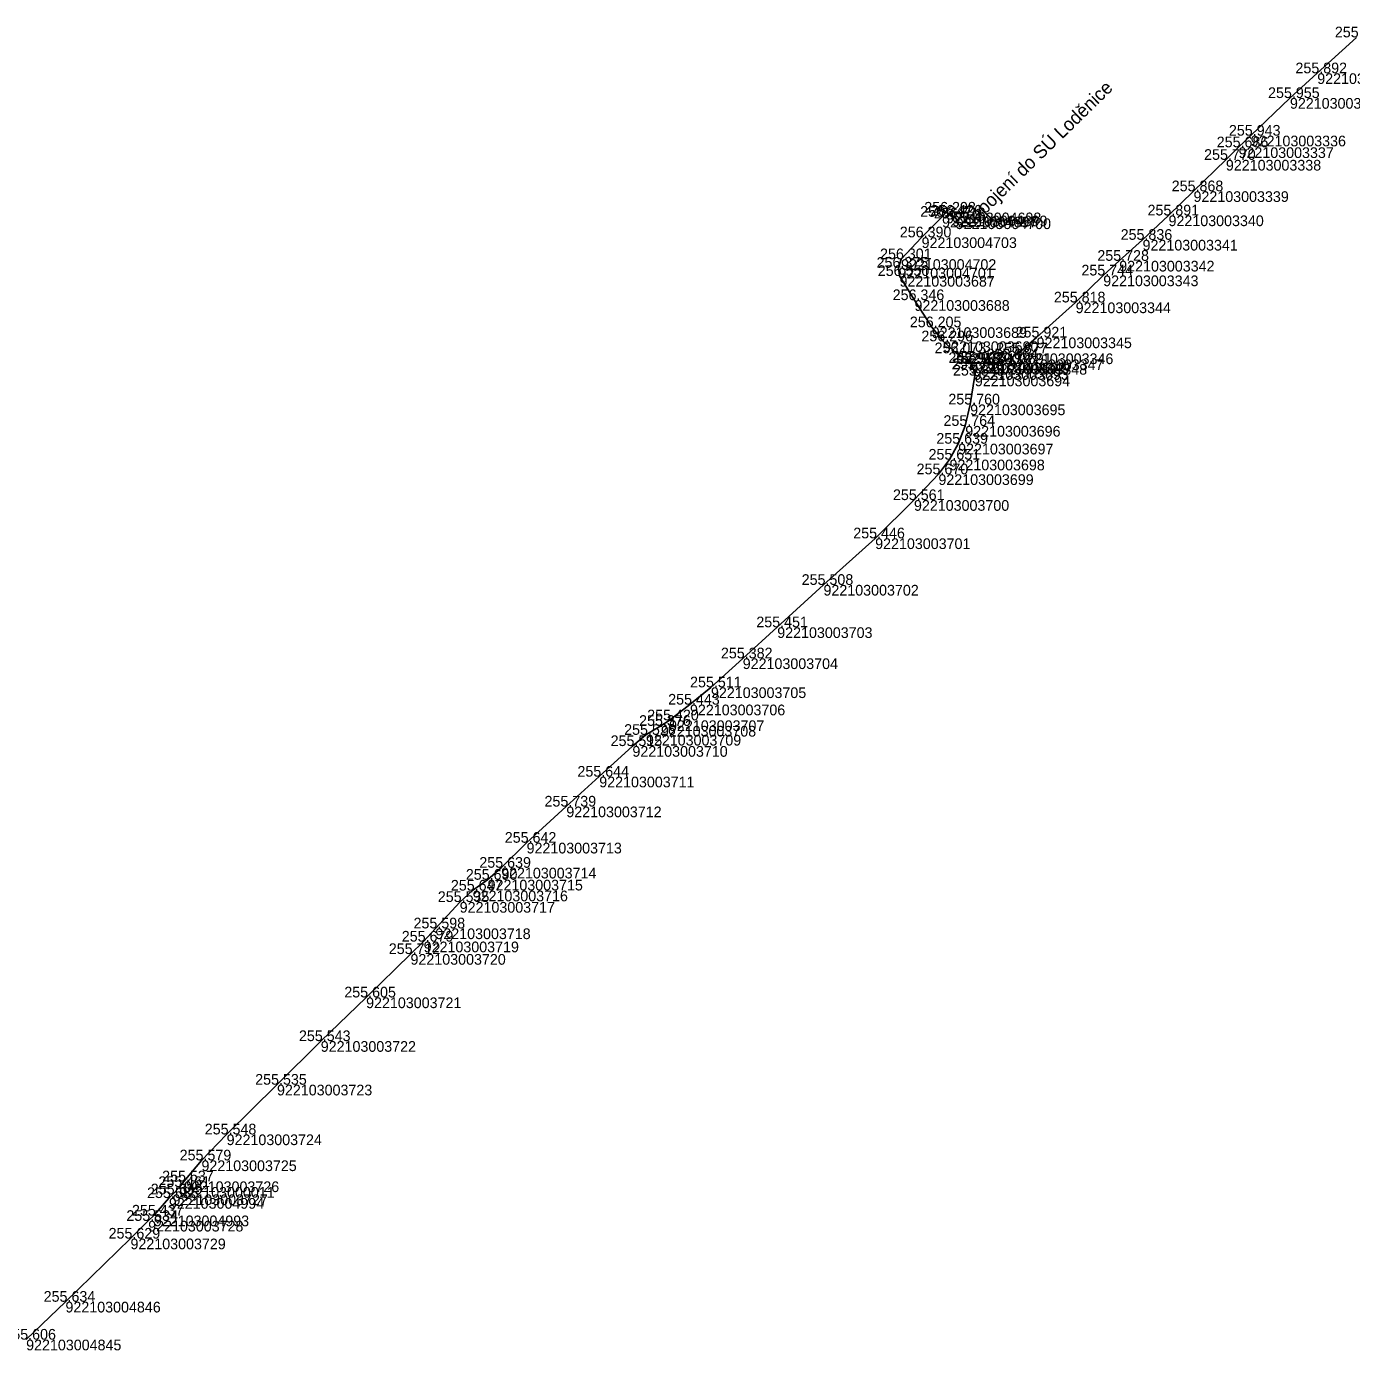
# Model space of a CAD drawing. Extents: x -771047 to -756200, y -1053876 to -1046520.
# Drawn here: x -762711.4 to -762562.5, y -1050999.9 to -1050851.1 of the extents above; entities that cross this region are included whole.
import ezdxf

# ---------------------------------------------------------------- set-up
doc = ezdxf.new("R2010")
doc.units = 0
for name, color, linetype in [('Vrstva 32', 7, 'Continuous'), ('Vrstva 60', 7, 'Continuous'), ('Vrstva 61', 7, 'Continuous'), ('Vrstva 63', 7, 'Continuous')]:
    doc.layers.add(name, color=color, linetype=linetype)

msp = doc.modelspace()

# ---------------------------------------------------------------- linework, layer by layer
at = {"layer": 'Vrstva 32'}
for points in [[(-762561.91, -1050852.33), (-762566.34, -1050856.37), (-762569.41, -1050859.15), (-762573.82, -1050863.38), (-762575.19, -1050864.69), (-762576.61, -1050866.1), (-762580.25, -1050869.63), (-762583.06, -1050872.35), (-762585.98, -1050875.09), (-762588.6, -1050877.45), (-762590.4, -1050879.1), (-762593.5, -1050882.13), (-762597.89, -1050886.07), (-762599.97, -1050887.86), (-762601.08, -1050888.54), (-762602.92, -1050889.05), (-762604.85, -1050888.89), (-762605.34, -1050888.93)], [(-762608.07, -1050872.03), (-762608.52, -1050872.5), (-762610.82, -1050874.81), (-762613.13, -1050877.27), (-762613.42, -1050878.23), (-762613.3, -1050879.15), (-762611.62, -1050881.87), (-762609.68, -1050884.92), (-762608.39, -1050886.5), (-762606.91, -1050887.84), (-762605.34, -1050888.93), (-762604.98, -1050889.63), (-762604.83, -1050890.35), (-762605.36, -1050893.6), (-762605.91, -1050896.01), (-762606.71, -1050898.01), (-762607.68, -1050899.8), (-762608.93, -1050901.45), (-762611.68, -1050904.35), (-762616.04, -1050908.65), (-762621.85, -1050913.88), (-762627.05, -1050918.65), (-762630.93, -1050922.14), (-762634.5, -1050925.4), (-762636.86, -1050927.34), (-762639.21, -1050929.11), (-762640.13, -1050929.73), (-762641.81, -1050930.74), (-762643.33, -1050932), (-762647.06, -1050935.44), (-762650.76, -1050938.8), (-762655.23, -1050942.87), (-762658.09, -1050945.68), (-762659.61, -1050947.03), (-762661.29, -1050948.25), (-762662.75, -1050949.53), (-762665.48, -1050952.5), (-762666.8, -1050953.98), (-762668.28, -1050955.38), (-762673.27, -1050960.26), (-762678.37, -1050965.17), (-762683.29, -1050970.07), (-762688.95, -1050975.66), (-762691.78, -1050978.58), (-762693.75, -1050980.94), (-762694.26, -1050981.57), (-762695.03, -1050982.4), (-762695.44, -1050982.81), (-762697.13, -1050984.78), (-762697.77, -1050985.38), (-762699.76, -1050987.37), (-762707.07, -1050994.47), (-762711.49, -1050998.73)], [(-762608.07, -1050872.03), (-762607.38, -1050872.37), (-762606.98, -1050872.68)]]:
    msp.add_lwpolyline(points, dxfattribs=at)
at = {"layer": 'Vrstva 60'}
for p, q in [((-762566.34, -1050856.37), (-762566.34, -1050856.37)), ((-762569.41, -1050859.15), (-762569.41, -1050859.15)), ((-762573.82, -1050863.38), (-762573.82, -1050863.38)), ((-762576.61, -1050866.1), (-762576.61, -1050866.1)), ((-762575.19, -1050864.69), (-762575.19, -1050864.69)), ((-762580.25, -1050869.63), (-762580.25, -1050869.63)), ((-762608.07, -1050872.03), (-762608.07, -1050872.03)), ((-762608.52, -1050872.5), (-762608.52, -1050872.5)), ((-762607.38, -1050872.37), (-762607.38, -1050872.37)), ((-762606.98, -1050872.68), (-762606.98, -1050872.68)), ((-762583.06, -1050872.35), (-762583.06, -1050872.35)), ((-762610.82, -1050874.81), (-762610.82, -1050874.81)), ((-762585.98, -1050875.09), (-762585.98, -1050875.09)), ((-762613.13, -1050877.27), (-762613.13, -1050877.27)), ((-762588.6, -1050877.45), (-762588.6, -1050877.45)), ((-762613.42, -1050878.23), (-762613.42, -1050878.23)), ((-762613.3, -1050879.15), (-762613.3, -1050879.15)), ((-762590.4, -1050879.1), (-762590.4, -1050879.1)), ((-762611.62, -1050881.87), (-762611.62, -1050881.87)), ((-762593.5, -1050882.13), (-762593.5, -1050882.13)), ((-762609.68, -1050884.92), (-762609.68, -1050884.92)), ((-762608.39, -1050886.5), (-762608.39, -1050886.5)), ((-762597.89, -1050886.07), (-762597.89, -1050886.07)), ((-762606.91, -1050887.84), (-762606.91, -1050887.84)), ((-762599.97, -1050887.86), (-762599.97, -1050887.86)), ((-762605.34, -1050888.93), (-762605.34, -1050888.93)), ((-762604.98, -1050889.63), (-762604.98, -1050889.63)), ((-762604.85, -1050888.89), (-762604.85, -1050888.89)), ((-762602.92, -1050889.05), (-762602.92, -1050889.05)), ((-762601.08, -1050888.54), (-762601.08, -1050888.54)), ((-762604.83, -1050890.35), (-762604.83, -1050890.35)), ((-762605.36, -1050893.6), (-762605.36, -1050893.6)), ((-762605.91, -1050896.01), (-762605.91, -1050896.01)), ((-762606.71, -1050898.01), (-762606.71, -1050898.01)), ((-762607.68, -1050899.8), (-762607.68, -1050899.8)), ((-762608.93, -1050901.45), (-762608.93, -1050901.45)), ((-762611.68, -1050904.35), (-762611.68, -1050904.35)), ((-762616.04, -1050908.65), (-762616.04, -1050908.65)), ((-762621.85, -1050913.88), (-762621.85, -1050913.88)), ((-762627.05, -1050918.65), (-762627.05, -1050918.65)), ((-762630.93, -1050922.14), (-762630.93, -1050922.14)), ((-762634.5, -1050925.4), (-762634.5, -1050925.4)), ((-762636.86, -1050927.34), (-762636.86, -1050927.34)), ((-762640.13, -1050929.73), (-762640.13, -1050929.73)), ((-762639.21, -1050929.11), (-762639.21, -1050929.11)), ((-762641.81, -1050930.74), (-762641.81, -1050930.74)), ((-762643.33, -1050932), (-762643.33, -1050932)), ((-762647.06, -1050935.44), (-762647.06, -1050935.44)), ((-762650.76, -1050938.8), (-762650.76, -1050938.8)), ((-762655.23, -1050942.87), (-762655.23, -1050942.87)), ((-762658.09, -1050945.68), (-762658.09, -1050945.68)), ((-762659.61, -1050947.03), (-762659.61, -1050947.03)), ((-762662.75, -1050949.53), (-762662.75, -1050949.53)), ((-762661.29, -1050948.25), (-762661.29, -1050948.25)), ((-762665.48, -1050952.5), (-762665.48, -1050952.5)), ((-762666.8, -1050953.98), (-762666.8, -1050953.98)), ((-762668.28, -1050955.38), (-762668.28, -1050955.38)), ((-762673.27, -1050960.26), (-762673.27, -1050960.26)), ((-762678.37, -1050965.17), (-762678.37, -1050965.17)), ((-762683.29, -1050970.07), (-762683.29, -1050970.07)), ((-762688.95, -1050975.66), (-762688.95, -1050975.66)), ((-762691.78, -1050978.58), (-762691.78, -1050978.58)), ((-762694.26, -1050981.57), (-762694.26, -1050981.57)), ((-762693.75, -1050980.94), (-762693.75, -1050980.94)), ((-762695.44, -1050982.81), (-762695.44, -1050982.81)), ((-762695.03, -1050982.4), (-762695.03, -1050982.4)), ((-762697.13, -1050984.78), (-762697.13, -1050984.78)), ((-762697.77, -1050985.38), (-762697.77, -1050985.38)), ((-762699.76, -1050987.37), (-762699.76, -1050987.37)), ((-762707.07, -1050994.47), (-762707.07, -1050994.47))]:
    msp.add_line(p, q, dxfattribs=at)

# ---------------------------------------------------------------- texts
for s, p in [('922103003334', (-762566.34, -1050857.57)), ('922103003335', (-762569.41, -1050860.35)), ('922103003336', (-762573.82, -1050864.58)), ('922103003338', (-762576.61, -1050867.3)), ('922103003337', (-762575.19, -1050865.89)), ('922103003339', (-762580.25, -1050870.83)), ('922103004698', (-762608.07, -1050873.23)), ('922103004697', (-762608.52, -1050873.7)), ('922103004699', (-762607.38, -1050873.57)), ('922103004700', (-762606.98, -1050873.88)), ('922103003340', (-762583.06, -1050873.55)), ('922103004703', (-762610.82, -1050876.01)), ('922103003341', (-762585.98, -1050876.29)), ('922103004702', (-762613.13, -1050878.47)), ('922103003342', (-762588.6, -1050878.65)), ('922103004701', (-762613.42, -1050879.43)), ('922103003687', (-762613.3, -1050880.35)), ('922103003343', (-762590.4, -1050880.3)), ('922103003688', (-762611.62, -1050883.07)), ('922103003344', (-762593.5, -1050883.33)), ('922103003689', (-762609.68, -1050886.12)), ('922103003690', (-762608.39, -1050887.7)), ('922103003345', (-762597.89, -1050887.27)), ('922103003691', (-762606.91, -1050889.04)), ('922103003346', (-762599.97, -1050889.06)), ('922103003692', (-762605.34, -1050890.13)), ('922103003693', (-762604.98, -1050890.83)), ('922103003349', (-762604.85, -1050890.09)), ('922103003348', (-762602.92, -1050890.25)), ('922103003347', (-762601.08, -1050889.74)), ('922103003694', (-762604.83, -1050891.55)), ('922103003695', (-762605.36, -1050894.8)), ('922103003696', (-762605.91, -1050897.21)), ('922103003697', (-762606.71, -1050899.21)), ('922103003698', (-762607.68, -1050901)), ('922103003699', (-762608.93, -1050902.65)), ('922103003700', (-762611.68, -1050905.55)), ('922103003701', (-762616.04, -1050909.85)), ('922103003702', (-762621.85, -1050915.08)), ('922103003703', (-762627.05, -1050919.85)), ('922103003704', (-762630.93, -1050923.34)), ('922103003705', (-762634.5, -1050926.6)), ('922103003706', (-762636.86, -1050928.54)), ('922103003708', (-762640.13, -1050930.93)), ('922103003707', (-762639.21, -1050930.31)), ('922103003709', (-762641.81, -1050931.94)), ('922103003710', (-762643.33, -1050933.2)), ('922103003711', (-762647.06, -1050936.64)), ('922103003712', (-762650.76, -1050940)), ('922103003713', (-762655.23, -1050944.07)), ('922103003714', (-762658.09, -1050946.88)), ('922103003715', (-762659.61, -1050948.23)), ('922103003717', (-762662.75, -1050950.73)), ('922103003716', (-762661.29, -1050949.45)), ('922103003718', (-762665.48, -1050953.7)), ('922103003719', (-762666.8, -1050955.18)), ('922103003720', (-762668.28, -1050956.58)), ('922103003721', (-762673.27, -1050961.46)), ('922103003722', (-762678.37, -1050966.37)), ('922103003723', (-762683.29, -1050971.27)), ('922103003724', (-762688.95, -1050976.86)), ('922103003725', (-762691.78, -1050979.78)), ('922103000011', (-762694.26, -1050982.77)), ('922103003726', (-762693.75, -1050982.14)), ('922103004994', (-762695.44, -1050984.01)), ('922103003727', (-762695.03, -1050983.6)), ('922103004993', (-762697.13, -1050985.98)), ('922103003728', (-762697.77, -1050986.57)), ('922103003729', (-762699.76, -1050988.57)), ('922103004846', (-762707.07, -1050995.67)), ('922103004845', (-762711.49, -1050999.93))]:
    msp.add_text(s, height=1.2, dxfattribs=at).set_placement(p)
at = {"layer": 'Vrstva 61'}
for s, p in [('255.822', (-762564.36, -1050852.33)), ('255.892', (-762568.79, -1050856.37)), ('255.955', (-762571.87, -1050859.15)), ('255.943', (-762576.27, -1050863.38)), ('255.686', (-762577.64, -1050864.69)), ('255.770', (-762579.06, -1050866.1)), ('255.868', (-762582.7, -1050869.63)), ('256.347', (-762610.98, -1050872.5)), ('256.298', (-762610.52, -1050872.03)), ('256.426', (-762609.83, -1050872.37)), ('256.518', (-762609.44, -1050872.68)), ('255.891', (-762585.42, -1050872.35)), ('256.390', (-762613.27, -1050874.81)), ('255.836', (-762588.44, -1050875.09)), ('256.301', (-762615.49, -1050877.27)), ('255.728', (-762591.06, -1050877.45)), ('256.375', (-762615.88, -1050878.23)), ('256.550', (-762615.75, -1050879.15)), ('255.744', (-762592.85, -1050879.1)), ('256.346', (-762614.07, -1050881.87)), ('255.818', (-762595.95, -1050882.13)), ('256.205', (-762612.14, -1050884.92)), ('256.296', (-762610.84, -1050886.5)), ('255.921', (-762600.25, -1050886.07)), ('256.073', (-762609.36, -1050887.84)), ('255.877', (-762602.43, -1050887.86)), ('255.918', (-762607.8, -1050888.93)), ('255.793', (-762607.43, -1050889.63)), ('255.937', (-762607.31, -1050888.89)), ('255.943', (-762605.37, -1050889.05)), ('255.864', (-762603.53, -1050888.54)), ('255.845', (-762607.29, -1050890.35)), ('255.760', (-762607.81, -1050893.6)), ('255.764', (-762608.36, -1050896.01)), ('255.639', (-762609.16, -1050898.01)), ('255.651', (-762610.04, -1050899.8)), ('255.670', (-762611.38, -1050901.45)), ('255.561', (-762614.04, -1050904.35)), ('255.446', (-762618.5, -1050908.65)), ('255.508', (-762624.3, -1050913.88)), ('255.451', (-762629.4, -1050918.65)), ('255.382', (-762633.38, -1050922.14)), ('255.511', (-762636.85, -1050925.4)), ('255.443', (-762639.31, -1050927.34)), ('255.376', (-762642.58, -1050929.73)), ('255.420', (-762641.67, -1050929.11)), ('255.526', (-762644.26, -1050930.74)), ('255.515', (-762645.78, -1050932)), ('255.644', (-762649.51, -1050935.44)), ('255.739', (-762653.21, -1050938.8)), ('255.642', (-762657.68, -1050942.87)), ('255.639', (-762660.54, -1050945.68)), ('255.690', (-762662.06, -1050947.03)), ('255.647', (-762663.74, -1050948.25)), ('255.535', (-762665.21, -1050949.53)), ('255.598', (-762667.94, -1050952.5)), ('255.679', (-762669.26, -1050953.98)), ('255.712', (-762670.72, -1050955.38)), ('255.605', (-762675.72, -1050960.26)), ('255.543', (-762680.82, -1050965.17)), ('255.535', (-762685.74, -1050970.07)), ('255.548', (-762691.41, -1050975.66)), ('255.579', (-762694.23, -1050978.58)), ('255.461', (-762696.62, -1050981.57)), ('255.537', (-762696.2, -1050980.94)), ('255.585', (-762697.9, -1050982.81)), ('255.539', (-762697.48, -1050982.4)), ('255.437', (-762699.59, -1050984.78)), ('255.534', (-762700.22, -1050985.38)), ('255.629', (-762702.22, -1050987.37)), ('255.634', (-762709.52, -1050994.47)), ('255.606', (-762713.94, -1050998.73))]:
    msp.add_text(s, height=1.2, dxfattribs=at).set_placement(p)
at = {"layer": 'Vrstva 63'}
msp.add_text('napojení do SÚ Loděnice', height=1.5, rotation=44.2987, dxfattribs=at).set_placement((-762605.33, -1050873.87))

doc.saveas('drawing.dxf')
